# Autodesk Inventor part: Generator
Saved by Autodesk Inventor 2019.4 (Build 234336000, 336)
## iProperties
Created: 2020-02
Part Number: Generator
Material: Generic
Document SubType Name: Modeling
Designer: Administrator
Density: 1 g/cm^3
Appearance: Default
Title: Generator
Author: Administrator
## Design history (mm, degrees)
feature "Body1"
body "Solid1"
